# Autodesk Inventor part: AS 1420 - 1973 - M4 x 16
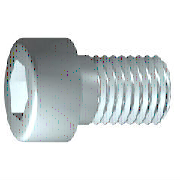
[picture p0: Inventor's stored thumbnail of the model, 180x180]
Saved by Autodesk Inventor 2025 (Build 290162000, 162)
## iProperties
Created: 2024-01
Part Number: AS 1420 - 1973 - M4 x 16
Material: Acciaio, Dolce
Description: Viti con esagono incassato metriche ISO
Document SubType Name: Modeling
Standard: AS 1420 - 1973
Designer: 18907419
Standards Organization: AS
Language: it-IT
Size Designation: M4 x 16
Categories: <MemberInstance><Categories><Category DisplayName="Elementi di fissaggio" InternalName="e4da775c-781d-43d5-af7c-5136215cf5a6" Mnemonic="FSTN"><Category DisplayN
Density: 7.85 g/cm^3
Appearance: Semilucidato
IsCustomPart: 0
Author: 18907419
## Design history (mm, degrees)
body "Solid1"
workplane "Work Plane1"
fillet "Fillet2" dims "d30" = 0.1 (= R)
revolve "Corpo" stored, may be unused: angle "d10" = 90 deg
sketch "Schizzo2"
  geometry: L1 (0, -4.9)-(0, 4.9) reference; L2 (-4.9, 0)-(4.9, 0) reference; L3 (1.732, 0)-(0.866, -1.5); L4 (0.866, -1.5)-(-0.866, -1.5); L5 (-0.866, -1.5)-(-1.732, 0); L6 (-1.732, 0)-(-0.866, 1.5); L7 (-0.866, 1.5)-(0.866, 1.5); L8 (0.866, 1.5)-(1.732, 0); 2 further points
  constraints: 12 end point, 1 coincident, 1 horizontal alignment, 1 point on line, 12 other
extrude "Intaglio" join sketch "Schizzo2" stored distance "d11" = 10; taper "d12" = 0 deg
fillet "Raccordo1" dims "d17" = 0.4 (= RR)
feature "Filettatura" dims "d13" = 14 (= GEL), "d14" = 0
chamfer "Smusso1" distance "d15" = 0.42941 (= -0.5 x SPD + 0.5 x GD); stored, may be unused: second distance "d16" = 0.42941 (= GUL), angle "d27" = 45 deg
sketch "Schizzo1"
  geometry: L1 (-1, 0)-(16, 0); L2 (16, 0)-(16, 2); L3 (16, 2)-(2, 2); L4 (2, 2)-(1.57, 2); L5 (1.57, 2)-(0, 2); L6 (0, 2)-(0, 3.5); L7 (0, 3.5)-(-4, 3.5); L8 (-4, 3.5)-(-4, 1.732); L9 (-4, 1.732)-(-2, 1.732); L10 (-2, 1.732)-(-1, 0); L11 (-8, 0)-(20, 0) reference; L12 (0, -0.7)-(0, 4.2) reference; L13 (2, 2)-(0, 2)
  constraints: 22 end point, 6 parallel, 2 collinear, 2 perpendicular, 1 horizontal, 1 point on line
  dimensions: "d1" = 14 distance from line of L3.end L2 (= GEL); "d2" = 0.42952 distance of L4.end L3.end (computed from GAL); "d3" = 4 distance between parallel lines of L8 L6 (= KOH); "d4" = 2 distance of L8.end L9.end (= INTI); "d5" = 60 deg angle of L10 L1; "d6" = 4 diameter of L3 L1 (= GD); "d7" = 4 diameter of L5 L1 (= BDM); "d8" = 3.4641 diameter of L9 L1 (= 1.1547 x SW); "d9" = 7 diameter of L7 L1 (= KOD); "d26" = 16 distance between parallel lines of L12 L2 (= NLG)
other parameters: "GD" = 4 (= NND) [user parameter; used in 2 equation terms], "NLG" = 16 [user parameter; used in 1 equation term], "GEL" = 14 [user parameter; used in 2 equation terms], "KOD" = 7 [user parameter; used in 1 equation term], "KOH" = 4 (= NND) [user parameter; used in 1 equation term], "INTI" = 2 [user parameter; used in 1 equation term], "GAL" = 0.42941 (= 0.61345 x PTC) [user parameter; used in 1 equation term], "GUL" = 0.42941 (= 0.61345 x PTC) [user parameter; used in 1 equation term], "BDM" = 4 (= NND) [user parameter; used in 1 equation term], "SW" = 3 [user parameter; used in 2 equation terms], "RR" = 0.4 (= 0.1 x NND) [user parameter; used in 1 equation term], "SPD" = 3.14117 (= NND - 1.2269 x PTC) [user parameter; used in 1 equation term], "d19" = 0, "d28" = 0, "d29" = 0, "R" = 0.1 [user parameter; used in 1 equation term], "PHH" = 0.13 [user parameter], "GD1" = 3.14117 (= THREADDIA - 1.2269 x PTC) [user parameter], "THREADDIA" = 4 [user parameter; used in 1 equation term], "FAWI" = 45 deg [user parameter], "TPU" = 14.28571 (computed from PTC) [user parameter], "PTC" = 0.7 [user parameter; used in 5 equation terms], "KOH1" = 3.6 [user parameter], "NND" = 4 [user parameter; used in 5 equation terms], "TOA" = 30 deg [user parameter], "E0" = 3.465 (= 1.155 x SW) [user parameter]
